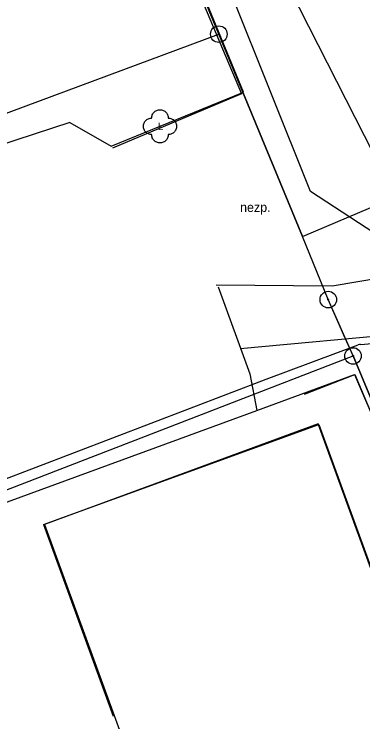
# Model space of a CAD drawing. Extents: x -834064 to -833847, y -1109181 to -1108930.
# Drawn here: x -833982.91 to -833961.89, y -1109135.96 to -1109093.27 of the extents above; entities that cross this region are included whole.
import ezdxf

# ---------------------------------------------------------------- set-up
doc = ezdxf.new("R2010")
doc.units = 0
for name, color, linetype in [('Budovy_hranice', 7, 'Continuous'), ('Hranice parcel', 7, 'Continuous'), ('OstPloch_hranice', 7, 'Continuous'), ('OstPloch_popis', 7, 'Continuous'), ('PROJEKT NN 0_4', 7, 'Continuous'), ('Stavby_linie', 7, 'Continuous'), ('Vrstva 17', 7, 'Continuous'), ('Vrstva 49', 7, 'Continuous'), ('Vrstva 51', 7, 'Continuous'), ('Vrstva 53', 7, 'Continuous'), ('Zelen_body', 7, 'Continuous'), ('Značky bodu BP', 7, 'Continuous')]:
    doc.layers.add(name, color=color, linetype=linetype)

msp = doc.modelspace()

# ---------------------------------------------------------------- linework, layer by layer
at = {"layer": 'Budovy_hranice'}
for p, q in [((-833981.132, -1109124.046), (-833964.539, -1109118.024)), ((-833964.539, -1109118.024), (-833959.174, -1109132.806)), ((-833981.132, -1109124.046), (-833976.936, -1109135.608))]:
    msp.add_line(p, q, dxfattribs=at)
at = {"layer": 'Hranice parcel'}
for p, q in [((-834006.84, -1109107.97), (-833970.57, -1109094.48)), ((-834006.84, -1109107.97), (-833970.57, -1109094.48)), ((-833970.57, -1109094.48), (-833965.53, -1109106.68)), ((-833970.57, -1109094.48), (-833965.53, -1109106.68))]:
    msp.add_line(p, q, dxfattribs=at)
for points in [[(-833982.044, -1109066.782), (-833981.08, -1109069.08), (-833970.57, -1109094.48)], [(-833976.392, -1109080.41), (-833970.57, -1109094.48)], [(-833965.53, -1109106.68), (-833952.5, -1109101.15), (-833951.04, -1109104.84)], [(-833965.53, -1109106.68), (-833952.5, -1109101.15), (-833951.04, -1109104.84)], [(-833962.48, -1109113.89), (-833963.03, -1109112.64), (-833963.97, -1109110.49), (-833965.53, -1109106.68)], [(-833962.48, -1109113.89), (-833963.03, -1109112.64), (-833963.97, -1109110.49), (-833965.53, -1109106.68)], [(-834004.833, -1109130.267), (-833962.48, -1109113.89)], [(-834004.833, -1109130.267), (-833962.48, -1109113.89)], [(-833962.48, -1109113.89), (-833941.85, -1109163.47), (-833941.739, -1109163.737)], [(-833962.48, -1109113.89), (-833941.85, -1109163.47), (-833941.739, -1109163.737)], [(-833947.114, -1109165.977), (-833964.59, -1109117.98), (-833981.08, -1109124.05), (-833963.334, -1109172.737)], [(-833947.114, -1109165.977), (-833964.59, -1109117.98), (-833981.08, -1109124.05), (-833963.334, -1109172.737)]]:
    msp.add_lwpolyline(points, dxfattribs=at)
at = {"layer": 'OstPloch_hranice'}
for p, q in [((-833970.62, -1109109.73), (-833968.7, -1109114.96)), ((-833968.7, -1109114.96), (-833968.27, -1109117.17))]:
    msp.add_line(p, q, dxfattribs=at)
at = {"layer": 'PROJEKT NN 0_4'}
for p, q in [((-833962.028, -1109113.193), (-833959.986, -1109113.027)), ((-833967.722, -1109115.292), (-833962.162, -1109113.223))]:
    msp.add_line(p, q, dxfattribs=at)
msp.add_lwpolyline([(-834005.109, -1109129.605), (-833990.844, -1109124.135), (-833967.722, -1109115.292)], dxfattribs=at)
msp.add_arc((-833961.988, -1109113.692), 0.5, 94.6517, 110.4112, dxfattribs=at)
at = {"layer": 'Stavby_linie'}
for p, q in [((-833969.09, -1109097.97), (-833974.89, -1109083.78)), ((-833977.06, -1109101.23), (-833969.09, -1109097.97)), ((-833979.56, -1109099.8), (-833987.08, -1109102.26)), ((-833979.56, -1109099.8), (-833977.06, -1109101.23)), ((-833968.27, -1109117.17), (-833962.4, -1109115)), ((-833962.4, -1109115), (-833957.68, -1109126.03)), ((-833994.31, -1109126.73), (-833968.27, -1109117.17))]:
    msp.add_line(p, q, dxfattribs=at)
at = {"layer": 'Vrstva 17'}
for points in [[(-833982.351, -1109066.91), (-833969.199, -1109098.089), (-833976.975, -1109101.352)], [(-833965.406, -1109116.185), (-833962.374, -1109115.013)], [(-833962.374, -1109115.013), (-833947.045, -1109151.363), (-833941.874, -1109163.794)]]:
    msp.add_lwpolyline(points, dxfattribs=at)
at = {"layer": 'Vrstva 49'}
for points in [[(-833977.837, -1109065.028), (-833970.211, -1109084.069), (-833960.118, -1109103.903)], [(-833965.045, -1109103.977), (-833972.17, -1109086.13), (-833980.691, -1109066.218)], [(-833959.255, -1109107.753), (-833965.045, -1109103.977)]]:
    msp.add_lwpolyline(points, dxfattribs=at)
at = {"layer": 'Vrstva 51'}
for points in [[(-833970.728, -1109109.603), (-833963.744, -1109109.661), (-833957.903, -1109108.677)], [(-833969.284, -1109113.442), (-833959.261, -1109112.507), (-833957.939, -1109118.413), (-833955.134, -1109126.136), (-833944.916, -1109150.188), (-833941.317, -1109157.071), (-833937.982, -1109162.172)]]:
    msp.add_lwpolyline(points, dxfattribs=at)
at = {"layer": 'Vrstva 53'}
for points in [[(-833965.53, -1109106.68), (-833970.57, -1109094.48), (-833981.08, -1109069.08), (-833982.044, -1109066.782)], [(-833941.736, -1109163.736), (-833962.48, -1109113.89), (-833963.97, -1109110.49), (-833965.53, -1109106.68)]]:
    msp.add_lwpolyline(points, dxfattribs=at)
at = {"layer": 'Zelen_body'}
msp.add_line((-833974.12, -1109100.04), (-833974.12, -1109100.04), dxfattribs=at)
for points in [[(-833974.62, -1109099.54), (-833974.618, -1109099.492), (-833974.61, -1109099.443), (-833974.598, -1109099.393), (-833974.58, -1109099.344), (-833974.556, -1109099.295), (-833974.527, -1109099.249), (-833974.493, -1109099.206), (-833974.454, -1109099.167), (-833974.411, -1109099.133), (-833974.365, -1109099.104), (-833974.316, -1109099.08), (-833974.267, -1109099.062), (-833974.217, -1109099.05), (-833974.168, -1109099.042), (-833974.12, -1109099.04), (-833974.072, -1109099.042), (-833974.023, -1109099.05), (-833973.973, -1109099.062), (-833973.924, -1109099.08), (-833973.875, -1109099.104), (-833973.829, -1109099.133), (-833973.786, -1109099.167), (-833973.747, -1109099.206), (-833973.713, -1109099.249), (-833973.684, -1109099.295), (-833973.66, -1109099.344), (-833973.642, -1109099.393), (-833973.63, -1109099.443), (-833973.622, -1109099.492), (-833973.62, -1109099.54)], [(-833974.62, -1109100.54), (-833974.668, -1109100.538), (-833974.717, -1109100.53), (-833974.767, -1109100.518), (-833974.816, -1109100.5), (-833974.865, -1109100.476), (-833974.911, -1109100.447), (-833974.954, -1109100.413), (-833974.993, -1109100.374), (-833975.027, -1109100.331), (-833975.056, -1109100.285), (-833975.08, -1109100.236), (-833975.098, -1109100.187), (-833975.11, -1109100.137), (-833975.118, -1109100.088), (-833975.12, -1109100.04), (-833975.118, -1109099.992), (-833975.11, -1109099.943), (-833975.098, -1109099.893), (-833975.08, -1109099.844), (-833975.056, -1109099.795), (-833975.027, -1109099.749), (-833974.993, -1109099.706), (-833974.954, -1109099.667), (-833974.911, -1109099.633), (-833974.865, -1109099.604), (-833974.816, -1109099.58), (-833974.767, -1109099.562), (-833974.717, -1109099.55), (-833974.668, -1109099.542), (-833974.62, -1109099.54)], [(-833973.62, -1109099.54), (-833973.572, -1109099.542), (-833973.523, -1109099.55), (-833973.473, -1109099.562), (-833973.424, -1109099.58), (-833973.375, -1109099.604), (-833973.329, -1109099.633), (-833973.286, -1109099.667), (-833973.247, -1109099.706), (-833973.213, -1109099.749), (-833973.184, -1109099.795), (-833973.16, -1109099.844), (-833973.142, -1109099.893), (-833973.13, -1109099.943), (-833973.122, -1109099.992), (-833973.12, -1109100.04), (-833973.122, -1109100.088), (-833973.13, -1109100.137), (-833973.142, -1109100.187), (-833973.16, -1109100.236), (-833973.184, -1109100.285), (-833973.213, -1109100.331), (-833973.247, -1109100.374), (-833973.286, -1109100.413), (-833973.329, -1109100.447), (-833973.375, -1109100.476), (-833973.424, -1109100.5), (-833973.473, -1109100.518), (-833973.523, -1109100.53), (-833973.572, -1109100.538), (-833973.62, -1109100.54)], [(-833973.62, -1109100.54), (-833973.622, -1109100.588), (-833973.63, -1109100.637), (-833973.642, -1109100.687), (-833973.66, -1109100.736), (-833973.684, -1109100.785), (-833973.713, -1109100.831), (-833973.747, -1109100.874), (-833973.786, -1109100.913), (-833973.829, -1109100.947), (-833973.875, -1109100.976), (-833973.924, -1109101), (-833973.973, -1109101.018), (-833974.023, -1109101.03), (-833974.072, -1109101.038), (-833974.12, -1109101.04), (-833974.168, -1109101.038), (-833974.217, -1109101.03), (-833974.267, -1109101.018), (-833974.316, -1109101), (-833974.365, -1109100.976), (-833974.411, -1109100.947), (-833974.454, -1109100.913), (-833974.493, -1109100.874), (-833974.527, -1109100.831), (-833974.556, -1109100.785), (-833974.58, -1109100.736), (-833974.598, -1109100.687), (-833974.61, -1109100.637), (-833974.618, -1109100.588), (-833974.62, -1109100.54)]]:
    msp.add_lwpolyline(points, dxfattribs=at)
msp.add_ellipse((-833974.12, -1109100.04), major_axis=(-0.0177, 0.0177), ratio=0.999997, dxfattribs=at)
at = {"layer": 'Značky bodu BP'}
for centre, radius in [((-833970.57, -1109094.48), 0.5), ((-833970.57, -1109094.48), 0.0303), ((-833963.97, -1109110.49), 0.5), ((-833963.97, -1109110.49), 0.0303), ((-833962.48, -1109113.89), 0.5), ((-833962.48, -1109113.89), 0.0303)]:
    msp.add_circle(centre, radius, dxfattribs=at)

# ---------------------------------------------------------------- texts
at = {"layer": 'OstPloch_popis'}
msp.add_text('nezp.', height=0.5625, dxfattribs=at).set_placement((-833969.289, -1109105.203))
at = {"layer": 'Zelen_body'}
msp.add_text('L', height=0.45, rotation=360, dxfattribs=at).set_placement((-833974.251, -1109100.265))

doc.saveas('drawing.dxf')
